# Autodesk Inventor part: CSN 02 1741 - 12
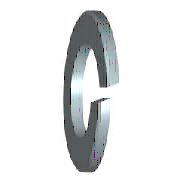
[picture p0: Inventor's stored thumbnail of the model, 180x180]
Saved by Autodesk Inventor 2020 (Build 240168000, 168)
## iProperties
Created: 2019-01
Part Number: CSN 02 1741 - 12
Material: Ocel, měkká
Description: Pružné podložky obdélníkového průřezu
Document SubType Name: Modeling
Standard: CSN 02 1741
Designer: doma
Standards Organization: CSN
Language: cs-CZ
Size Designation: 12
Categories: <MemberInstance><Categories><Category DisplayName="Spojovací materiál" InternalName="e4da775c-781d-43d5-af7c-5136215cf5a6" Mnemonic="FSTN"><Category DisplayName
Density: 7.85 g/cm^3
Appearance: Pololeštěná
IsCustomPart: 0
Author: doma
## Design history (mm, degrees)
sketch "Náčrt1"
  geometry: C1 r 10.1 at (0, 0); C2 r 6.1 at (0, 0); 1 further point
  constraints: 2 centre point, 2 coincident
  dimensions: "d0" = 12.2 diameter of C2 (= SD1); "d1" = 20.2 diameter of C1 (= SD2)
extrude "Těleso" new body sketch "Náčrt1" distance "d2" = 2.5 (= SD); taper "d3" = 0 deg
sketch "Náčrt2"
  geometry: L1 (0, -6.1)-(0, 6.1) reference; L2 (2.5, 10.1)-(2.5, -10.1) reference; L3 (-1.2, 0)-(7.2, 0) reference; L4 (0, -0.5)-(2.5, -0.059); L5 (0, 0.5)-(2.5, 0.941)
  constraints: 4 end point, 4 point on line, 1 parallel
  dimensions: "d4" = 0.5 distance from line of L3 L4.start (= 0.2 x SD); "d5" = 0.5 distance from line of L3 L5.start (= 0.2 x SD); "d6" = 80 deg angle of L2 L4 (= FAWI)
extrude "Výřez" cut sketch "Náčrt2" stored distance "d7" = 2.5 (= SD); taper "d8" = 0 deg
workaxis "Work Axis1"
workplane "Work Plane1"
body "Solid1"
other parameters: "SD1" = 12.2 [user parameter; used in 1 equation term], "SD2" = 20.2 [user parameter; used in 1 equation term], "SD" = 2.5 [user parameter; used in 4 equation terms], "FAWI" = 80 deg [user parameter; used in 1 equation term], "d9" = 0, "d10" = 0, "d11" = 0, "d12" = 0, "NND" = 12 [user parameter]
